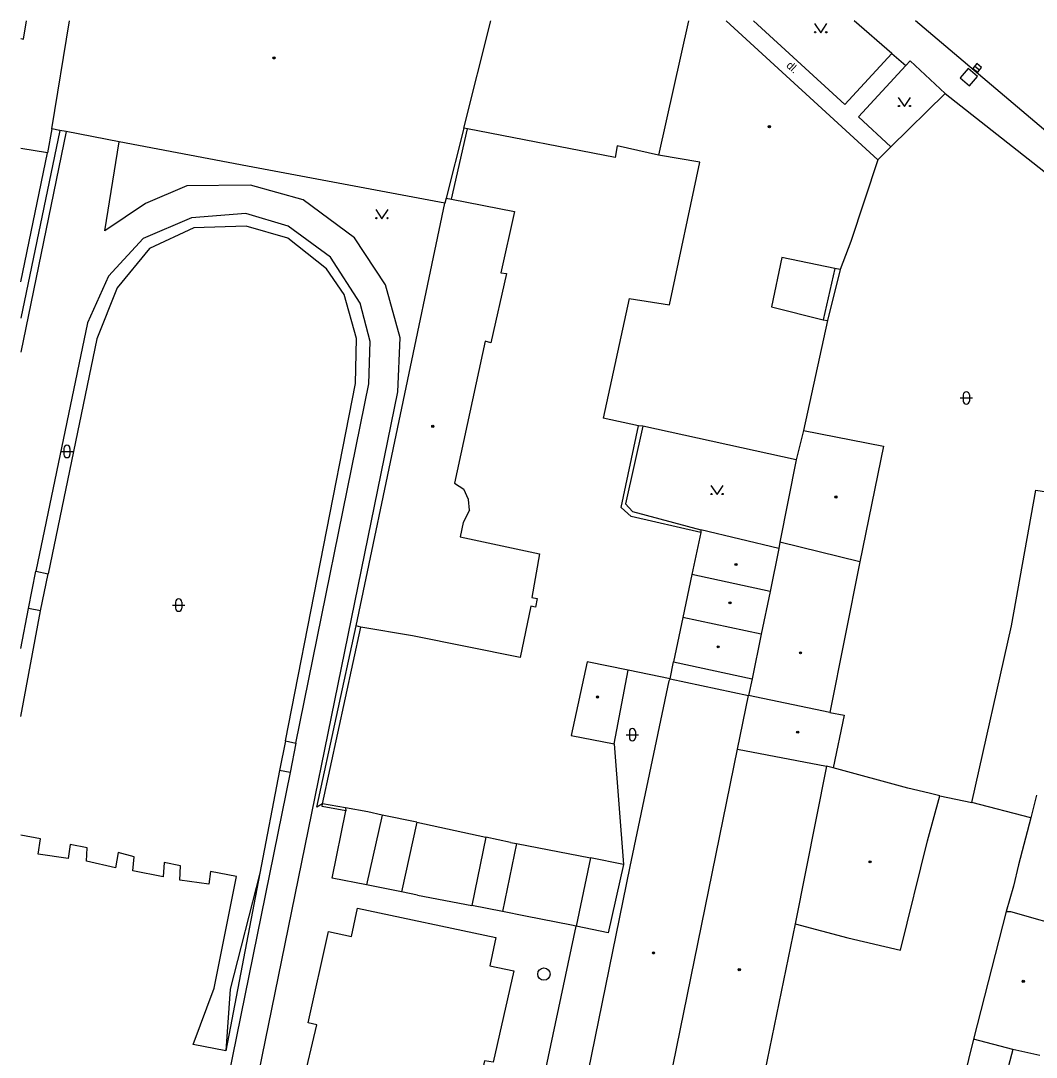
# Model space of a CAD drawing. Extents: x -598932 to -598196, y -1162207 to -1161504.
# Drawn here: x -598932 to -598849.5, y -1161589.4 to -1161505.2 of the extents above; entities that cross this region are included whole.
import ezdxf

# ---------------------------------------------------------------- set-up
doc = ezdxf.new("R2010")
doc.units = 0
for name, color, linetype in [('DOP - budovy nerozlisene - VP', 7, 'Continuous'), ('DOP - kresba z DSPS bez soueadnic', 7, 'Continuous'), ('DOP - rozhrani ploch obecne', 7, 'Continuous'), ('Level 26', 7, 'Continuous'), ('Level 27', 7, 'Continuous'), ('Level 36', 7, 'Continuous'), ('Level 39', 7, 'Continuous'), ('TM - budovy zdene_ betonove - VP', 7, 'Continuous'), ('TM - chodniky - VP', 7, 'Continuous'), ('TM - komunikace - VP', 7, 'Continuous'), ('TM - letecke snimky - pomocna linie', 7, 'Continuous'), ('TM - plot zdeny_ ohradni zed - VP', 7, 'Continuous'), ('TM - popis povrchu', 7, 'Continuous'), ('TM - rozhrani ploch obecne - VP', 7, 'Continuous')]:
    doc.layers.add(name, color=color, linetype=linetype)

msp = doc.modelspace()

# ---------------------------------------------------------------- linework, layer by layer
at = {"layer": 'DOP - budovy nerozlisene - VP'}
for points in [[(-598859.97, -1161567.52), (-598866.02, -1161565.87)], [(-598858.23, -1161567.94), (-598859.97, -1161567.52)], [(-598857.38, -1161568.16), (-598858.23, -1161567.94)], [(-598902.67, -1161569.72), (-598903.92, -1161575.39)], [(-598899.85, -1161570.3), (-598901.1, -1161575.95)], [(-598894.23, -1161571.52), (-598895.38, -1161577.06)], [(-598891.76, -1161572.02), (-598892.9, -1161577.54)], [(-598885.75, -1161573.2), (-598886.91, -1161578.75)], [(-598917.96, -1161612.26), (-598914.54, -1161614.14), (-598913.14, -1161611.53), (-598914.08, -1161611.13), (-598909.68, -1161591.58), (-598909.13, -1161591.69), (-598907.97, -1161586.75), (-598908.67, -1161586.59), (-598907.03, -1161579.17), (-598905.16, -1161579.58), (-598904.66, -1161577.29), (-598893.42, -1161579.66), (-598893.91, -1161581.97), (-598891.98, -1161582.38), (-598893.65, -1161589.78), (-598894.34, -1161589.68), (-598895.47, -1161594.7), (-598894.81, -1161594.85), (-598897.59, -1161607.46)]]:
    msp.add_lwpolyline(points, dxfattribs=at)
at = {"layer": 'DOP - kresba z DSPS bez soueadnic'}
for points in [[(-598928.84, -1161514.09), (-598932.017, -1161529.353)], [(-598928.32, -1161514.19), (-598932.017, -1161532.117)], [(-598897.03, -1161519.69), (-598895.72, -1161513.97)], [(-598925.19, -1161522.26), (-598924.03, -1161515.01)], [(-598918.53, -1161518.6), (-598921.88, -1161520.03)], [(-598913.35, -1161518.55), (-598918.53, -1161518.6)], [(-598909.08, -1161519.72), (-598913.35, -1161518.55)], [(-598921.88, -1161520.03), (-598925.19, -1161522.26)], [(-598904.92, -1161522.82), (-598909.08, -1161519.72)], [(-598913.73, -1161520.84), (-598918.15, -1161521.19)], [(-598910.3, -1161521.87), (-598913.73, -1161520.84)], [(-598918.15, -1161521.19), (-598922.07, -1161522.87)], [(-598917.97, -1161522), (-598921.56, -1161523.69)], [(-598913.71, -1161521.87), (-598917.97, -1161522)], [(-598910.32, -1161522.84), (-598913.71, -1161521.87)], [(-598906.85, -1161524.39), (-598910.3, -1161521.87)], [(-598922.07, -1161522.87), (-598924.88, -1161525.92)], [(-598907.18, -1161525.33), (-598910.32, -1161522.84)], [(-598902.39, -1161526.64), (-598904.92, -1161522.82)], [(-598921.56, -1161523.69), (-598924.18, -1161526.88)], [(-598904.44, -1161528.13), (-598906.85, -1161524.39)], [(-598924.88, -1161525.92), (-598926.59, -1161529.72)], [(-598905.76, -1161527.41), (-598907.18, -1161525.33)], [(-598865.9, -1161525.32), (-598866.84, -1161529.47)], [(-598924.18, -1161526.88), (-598925.84, -1161531.03)], [(-598901.2, -1161530.95), (-598902.39, -1161526.64)], [(-598904.74, -1161531.01), (-598905.76, -1161527.41)], [(-598903.63, -1161531.24), (-598904.44, -1161528.13)], [(-598926.59, -1161529.72), (-598930.78, -1161549.91)], [(-598925.84, -1161531.03), (-598929.8, -1161550.11)], [(-598904.84, -1161534.64), (-598904.74, -1161531.01)], [(-598901.38, -1161535.33), (-598901.2, -1161530.95)], [(-598903.75, -1161534.68), (-598903.63, -1161531.24)], [(-598910.52, -1161563.67), (-598904.84, -1161534.64)], [(-598909.68, -1161563.88), (-598903.75, -1161534.68)], [(-598914.03, -1161597.3), (-598901.38, -1161535.33)], [(-598883.25, -1161544.74), (-598881.85, -1161538.09)], [(-598881.5, -1161538.11), (-598882.91, -1161544.42)], [(-598882.91, -1161544.42), (-598882.33, -1161545.06)], [(-598882.45, -1161545.46), (-598883.25, -1161544.74)], [(-598882.33, -1161545.06), (-598876.77, -1161546.54)], [(-598876.78, -1161546.76), (-598882.45, -1161545.46)], [(-598931.38, -1161552.94), (-598930.78, -1161549.91)], [(-598930.78, -1161549.91), (-598929.8, -1161550.11)], [(-598930.4, -1161553.13), (-598929.8, -1161550.11)], [(-598932.017, -1161556.189), (-598931.38, -1161552.94)], [(-598930.4, -1161553.13), (-598931.38, -1161552.94)], [(-598932.017, -1161561.702), (-598930.4, -1161553.13)], [(-598907.51, -1161568.8), (-598904.39, -1161554.44)], [(-598910.52, -1161563.67), (-598911, -1161566.09)], [(-598910.52, -1161563.67), (-598909.68, -1161563.88)], [(-598909.68, -1161563.88), (-598910.12, -1161566.25)], [(-598910.12, -1161566.25), (-598916.18, -1161595.96)], [(-598911, -1161566.09), (-598912.59, -1161574.44)], [(-598910.12, -1161566.25), (-598911, -1161566.09)], [(-598907.54, -1161569.03), (-598907.51, -1161568.8)], [(-598905.62, -1161569.36), (-598907.54, -1161569.03)], [(-598930.42, -1161571.64), (-598932.017, -1161571.336)], [(-598930.61, -1161572.88), (-598930.42, -1161571.64)], [(-598928, -1161572.11), (-598928.16, -1161573.25)], [(-598926.63, -1161572.37), (-598928, -1161572.11)], [(-598928.16, -1161573.25), (-598930.61, -1161572.88)], [(-598926.68, -1161573.46), (-598926.63, -1161572.37)], [(-598924.1, -1161572.76), (-598924.32, -1161573.99)], [(-598922.81, -1161573.1), (-598924.1, -1161572.76)], [(-598922.9, -1161574.25), (-598922.81, -1161573.1)], [(-598924.32, -1161573.99), (-598926.68, -1161573.46)], [(-598920.37, -1161573.57), (-598920.46, -1161574.72)], [(-598919.04, -1161573.83), (-598920.37, -1161573.57)], [(-598919.09, -1161574.99), (-598919.04, -1161573.83)], [(-598920.46, -1161574.72), (-598922.9, -1161574.25)], [(-598916.6, -1161574.29), (-598916.73, -1161575.34)], [(-598914.48, -1161574.7), (-598916.6, -1161574.29)], [(-598916.3, -1161583.77), (-598914.48, -1161574.7)], [(-598912.59, -1161574.44), (-598915.36, -1161588.86)], [(-598912.59, -1161574.44), (-598915.02, -1161583.85)], [(-598916.73, -1161575.34), (-598919.09, -1161574.99)], [(-598918.02, -1161588.36), (-598916.3, -1161583.77)], [(-598915.02, -1161583.85), (-598915.36, -1161588.86)], [(-598915.36, -1161588.86), (-598918.02, -1161588.36)]]:
    msp.add_lwpolyline(points, dxfattribs=at)
at = {"layer": 'DOP - rozhrani ploch obecne'}
for points in [[(-598932.017, -1161526.398), (-598929.847, -1161515.902)], [(-598865.45, -1161525.39), (-598866.48, -1161529.54)], [(-598907.97, -1161569.08), (-598904.76, -1161554.35)], [(-598879.28, -1161558.65), (-598882.67, -1161557.94)], [(-598879.28, -1161558.65), (-598878.99, -1161557.27)], [(-598883.82, -1161563.92), (-598883.07, -1161573.72)], [(-598907.51, -1161568.8), (-598907.97, -1161569.08)], [(-598905.64, -1161569.12), (-598907.51, -1161568.8)], [(-598891.02, -1161598.13), (-598886.91, -1161578.75)]]:
    msp.add_lwpolyline(points, dxfattribs=at)
at = {"layer": 'Level 26'}
msp.add_lwpolyline([(-598855.725, -1161509.814), (-598854.966, -1161510.465), (-598854.315, -1161509.706), (-598855.074, -1161509.055)], close=True, dxfattribs=at)
at = {"layer": 'Level 27'}
msp.add_line((-598854.526, -1161508.865), (-598854.134, -1161509.175), dxfattribs=at)
msp.add_lwpolyline([(-598854.681, -1161509.062), (-598854.288, -1161509.371), (-598853.979, -1161508.978), (-598854.372, -1161508.669)], close=True, dxfattribs=at)
msp.add_circle((-598889.52, -1161582.63), 0.5, dxfattribs=at)
at = {"layer": 'Level 36'}
for p, q in [((-598855.716, -1161535.826), (-598854.716, -1161535.826)), ((-598855.466, -1161535.576), (-598855.466, -1161536.076)), ((-598854.966, -1161535.576), (-598854.966, -1161536.076)), ((-598928.766, -1161540.176), (-598927.766, -1161540.176)), ((-598928.516, -1161539.926), (-598928.516, -1161540.426)), ((-598928.016, -1161539.926), (-598928.016, -1161540.426)), ((-598919.686, -1161552.656), (-598918.686, -1161552.656)), ((-598919.436, -1161552.406), (-598919.436, -1161552.906)), ((-598918.936, -1161552.406), (-598918.936, -1161552.906)), ((-598882.586, -1161562.936), (-598882.586, -1161563.436)), ((-598882.086, -1161562.936), (-598882.086, -1161563.436)), ((-598882.836, -1161563.186), (-598881.836, -1161563.186))]:
    msp.add_line(p, q, dxfattribs=at)
for points in [[(-598867.54, -1161505.42), (-598867.04, -1161506.17), (-598866.54, -1161505.42)], [(-598860.74, -1161511.41), (-598860.24, -1161512.16), (-598859.74, -1161511.41)], [(-598903.18, -1161520.52), (-598902.68, -1161521.27), (-598902.18, -1161520.52)], [(-598875.96, -1161542.93), (-598875.46, -1161543.68), (-598874.96, -1161542.93)]]:
    msp.add_lwpolyline(points, dxfattribs=at)
for centre in [(-598867.49, -1161506.12), (-598866.591, -1161506.12), (-598860.69, -1161512.11), (-598859.791, -1161512.11), (-598903.13, -1161521.22), (-598902.231, -1161521.22), (-598875.91, -1161543.63), (-598875.011, -1161543.63)]:
    msp.add_circle(centre, 0.05, dxfattribs=at)
for centre, start, end in [((-598855.216, -1161535.576), 0, 180), ((-598855.216, -1161536.076), 180, 0), ((-598928.266, -1161539.926), 0, 180), ((-598928.266, -1161540.426), 180, 0), ((-598919.186, -1161552.406), 0, 180), ((-598919.186, -1161552.906), 180, 0), ((-598882.336, -1161562.936), 0, 180), ((-598882.336, -1161563.436), 180, 0)]:
    msp.add_arc(centre, 0.25, start, end, dxfattribs=at)
at = {"layer": 'Level 39'}
for centre, radius in [((-598911.45, -1161508.2), 0.09), ((-598911.45, -1161508.2), 0.0398), ((-598871.21, -1161513.78), 0.09), ((-598871.21, -1161513.78), 0.0398), ((-598898.55, -1161538.13), 0.09), ((-598898.55, -1161538.13), 0.0398), ((-598865.81, -1161543.87), 0.09), ((-598865.81, -1161543.87), 0.0398), ((-598873.93, -1161549.36), 0.09), ((-598873.93, -1161549.36), 0.0398), ((-598874.41, -1161552.47), 0.09), ((-598874.41, -1161552.47), 0.0398), ((-598875.37, -1161556.05), 0.09), ((-598875.37, -1161556.05), 0.0398), ((-598868.68, -1161556.53), 0.09), ((-598868.68, -1161556.53), 0.0398), ((-598885.17, -1161560.12), 0.09), ((-598885.17, -1161560.12), 0.0398), ((-598868.91, -1161562.98), 0.09), ((-598868.91, -1161562.98), 0.0398), ((-598863.03, -1161573.51), 0.09), ((-598863.03, -1161573.51), 0.0398), ((-598880.62, -1161580.91), 0.09), ((-598880.62, -1161580.91), 0.0398), ((-598873.66, -1161582.27), 0.09), ((-598873.66, -1161582.27), 0.0398), ((-598850.59, -1161583.22), 0.09), ((-598850.59, -1161583.22), 0.0398)]:
    msp.add_circle(centre, radius, dxfattribs=at)
at = {"layer": 'TM - budovy zdene_ betonove - VP'}
for points in [[(-598929.5, -1161513.96), (-598928.053, -1161505.182)], [(-598896.03, -1161513.91), (-598893.826, -1161505.182)], [(-598877.786, -1161505.182), (-598880.21, -1161516.09)], [(-598874.727, -1161505.182), (-598862.41, -1161516.47)], [(-598928.84, -1161514.09), (-598929.5, -1161513.96)], [(-598928.32, -1161514.19), (-598928.84, -1161514.09)], [(-598924.03, -1161515.01), (-598928.32, -1161514.19)], [(-598896.03, -1161513.91), (-598897.46, -1161519.61)], [(-598895.72, -1161513.97), (-598896.03, -1161513.91)], [(-598883.75, -1161516.3), (-598895.72, -1161513.97)], [(-598913.6, -1161516.99), (-598924.03, -1161515.01)], [(-598883.57, -1161515.34), (-598883.75, -1161516.3)], [(-598880.21, -1161516.09), (-598883.57, -1161515.34)], [(-598876.86, -1161516.68), (-598880.21, -1161516.09)], [(-598879.33, -1161528.27), (-598876.86, -1161516.68)], [(-598862.41, -1161516.47), (-598864.6, -1161523.13)], [(-598897.56, -1161520.01), (-598913.6, -1161516.99)], [(-598904.76, -1161554.35), (-598897.56, -1161520.01)], [(-598897.46, -1161519.61), (-598897.56, -1161520.01)], [(-598897.46, -1161519.61), (-598897.03, -1161519.69)], [(-598897.03, -1161519.69), (-598891.9, -1161520.69)], [(-598891.9, -1161520.69), (-598893.01, -1161525.66)], [(-598864.6, -1161523.13), (-598865.45, -1161525.39)], [(-598870.2, -1161524.41), (-598871.04, -1161528.42)], [(-598865.9, -1161525.32), (-598870.2, -1161524.41)], [(-598892.57, -1161525.71), (-598893.84, -1161531.36)], [(-598893.01, -1161525.66), (-598892.57, -1161525.71)], [(-598865.45, -1161525.39), (-598865.9, -1161525.32)], [(-598882.6, -1161527.74), (-598884.7, -1161537.48)], [(-598882.6, -1161527.74), (-598879.33, -1161528.27)], [(-598871.04, -1161528.42), (-598866.84, -1161529.47)], [(-598866.48, -1161529.54), (-598868.44, -1161538.47)], [(-598866.84, -1161529.47), (-598866.48, -1161529.54)], [(-598894.3, -1161531.22), (-598896.78, -1161542.75)], [(-598893.84, -1161531.36), (-598894.3, -1161531.22)], [(-598881.85, -1161538.09), (-598884.7, -1161537.48)], [(-598881.5, -1161538.11), (-598881.85, -1161538.09)], [(-598869.03, -1161540.86), (-598881.5, -1161538.11)], [(-598868.44, -1161538.47), (-598869.03, -1161540.86)], [(-598868.44, -1161538.47), (-598861.94, -1161539.74)], [(-598861.94, -1161539.74), (-598863.86, -1161549.13)], [(-598869.03, -1161540.86), (-598870.35, -1161547.54)], [(-598896.78, -1161542.75), (-598896.04, -1161543.25)], [(-598895.65, -1161544.07), (-598896.04, -1161543.25)], [(-598851.54, -1161554.33), (-598849.56, -1161543.31)], [(-598895.57, -1161544.94), (-598895.65, -1161544.07)], [(-598895.57, -1161544.94), (-598896.09, -1161545.95)], [(-598896.09, -1161545.95), (-598896.33, -1161547.11)], [(-598876.78, -1161546.76), (-598877.5, -1161550.18)], [(-598876.77, -1161546.54), (-598876.78, -1161546.76)], [(-598870.44, -1161548.05), (-598876.77, -1161546.54)], [(-598896.33, -1161547.11), (-598889.88, -1161548.49)], [(-598870.35, -1161547.54), (-598870.44, -1161548.05)], [(-598863.86, -1161549.13), (-598870.35, -1161547.54)], [(-598889.88, -1161548.49), (-598890.5, -1161552.04)], [(-598870.44, -1161548.05), (-598871.16, -1161551.54)], [(-598863.86, -1161549.13), (-598866.29, -1161561.39)], [(-598877.5, -1161550.18), (-598878.23, -1161553.65)], [(-598871.16, -1161551.54), (-598877.5, -1161550.18)], [(-598890.5, -1161552.04), (-598890.06, -1161552.13)], [(-598890.06, -1161552.13), (-598890.2, -1161552.83)], [(-598871.16, -1161551.54), (-598871.88, -1161555.02)], [(-598890.59, -1161552.73), (-598891.46, -1161556.91)], [(-598890.2, -1161552.83), (-598890.59, -1161552.73)], [(-598878.23, -1161553.65), (-598878.99, -1161557.27)], [(-598871.88, -1161555.02), (-598878.23, -1161553.65)], [(-598904.39, -1161554.44), (-598904.76, -1161554.35)], [(-598900.2, -1161555.16), (-598904.39, -1161554.44)], [(-598854.78, -1161568.68), (-598851.54, -1161554.33)], [(-598891.46, -1161556.91), (-598900.2, -1161555.16)], [(-598871.88, -1161555.02), (-598872.62, -1161558.64)], [(-598886.01, -1161557.26), (-598887.32, -1161563.24)], [(-598882.67, -1161557.94), (-598886.01, -1161557.26)], [(-598883.82, -1161563.92), (-598882.67, -1161557.94)], [(-598878.99, -1161557.27), (-598872.62, -1161558.64)], [(-598882.51, -1161573.88), (-598879.34, -1161558.81)], [(-598879.34, -1161558.81), (-598879.28, -1161558.65)], [(-598879.28, -1161558.65), (-598872.91, -1161560.01)], [(-598872.62, -1161558.64), (-598872.91, -1161560.01)], [(-598873.81, -1161564.36), (-598872.91, -1161560.01)], [(-598866.29, -1161561.39), (-598872.91, -1161560.01)], [(-598866.29, -1161561.39), (-598865.15, -1161561.59)], [(-598865.15, -1161561.59), (-598866.02, -1161565.87)], [(-598887.32, -1161563.24), (-598883.82, -1161563.92)], [(-598881.66, -1161602.9), (-598873.81, -1161564.36)], [(-598873.81, -1161564.36), (-598866.56, -1161565.74)], [(-598866.56, -1161565.74), (-598869.12, -1161578.54)], [(-598866.02, -1161565.87), (-598866.56, -1161565.74)], [(-598849.51, -1161568.11), (-598849.98, -1161569.95)], [(-598858.38, -1161571.81), (-598857.38, -1161568.16)], [(-598857.38, -1161568.16), (-598854.78, -1161568.68)], [(-598849.98, -1161569.95), (-598854.78, -1161568.68)], [(-598906.73, -1161574.83), (-598905.62, -1161569.36)], [(-598905.64, -1161569.12), (-598905.62, -1161569.36)], [(-598903.82, -1161569.46), (-598905.64, -1161569.12)], [(-598902.67, -1161569.72), (-598903.82, -1161569.46)], [(-598899.85, -1161570.3), (-598902.67, -1161569.72)], [(-598899.85, -1161570.3), (-598894.23, -1161571.52)], [(-598849.98, -1161569.95), (-598850.97, -1161573.77)], [(-598892.23, -1161571.95), (-598894.23, -1161571.52)], [(-598892.23, -1161571.95), (-598891.76, -1161572.02)], [(-598891.76, -1161572.02), (-598885.75, -1161573.2)], [(-598860.56, -1161580.69), (-598858.38, -1161571.81)], [(-598887.6, -1161598.85), (-598882.51, -1161573.88)], [(-598883.07, -1161573.72), (-598885.75, -1161573.2)], [(-598883.07, -1161573.72), (-598884.31, -1161579.29)], [(-598850.97, -1161573.77), (-598851.39, -1161575.5)], [(-598903.92, -1161575.39), (-598906.73, -1161574.83)], [(-598901.1, -1161575.95), (-598903.92, -1161575.39)], [(-598851.39, -1161575.5), (-598851.99, -1161577.55)], [(-598899.78, -1161576.21), (-598901.1, -1161575.95)], [(-598899.78, -1161576.21), (-598895.38, -1161577.06)], [(-598892.9, -1161577.54), (-598895.38, -1161577.06)], [(-598891.01, -1161577.92), (-598892.9, -1161577.54)], [(-598887.29, -1161578.67), (-598891.01, -1161577.92)], [(-598851.99, -1161577.55), (-598854.63, -1161587.92)], [(-598851.99, -1161577.55), (-598851.63, -1161577.55)], [(-598851.63, -1161577.55), (-598846.68, -1161578.95)], [(-598886.91, -1161578.75), (-598887.29, -1161578.67)], [(-598884.31, -1161579.29), (-598886.91, -1161578.75)], [(-598869.12, -1161578.54), (-598871.58, -1161590.53)], [(-598869.12, -1161578.54), (-598864.83, -1161579.7)], [(-598864.83, -1161579.7), (-598860.56, -1161580.69)], [(-598854.63, -1161587.92), (-598857.08, -1161597.83)], [(-598851.44, -1161588.77), (-598854.63, -1161587.92)], [(-598851.44, -1161588.77), (-598852.27, -1161591.92)], [(-598849.25, -1161589.24), (-598851.44, -1161588.77)]]:
    msp.add_lwpolyline(points, dxfattribs=at)
at = {"layer": 'TM - chodniky - VP'}
for points in [[(-598872.504, -1161505.182), (-598865.08, -1161511.99)], [(-598861.27, -1161507.84), (-598864.335, -1161505.182)], [(-598865.08, -1161511.99), (-598861.27, -1161507.84)], [(-598860.14, -1161508.82), (-598863.97, -1161513), (-598861.34, -1161515.42)], [(-598856.93, -1161511.1), (-598859.78, -1161508.43), (-598860.14, -1161508.82)]]:
    msp.add_lwpolyline(points, dxfattribs=at)
at = {"layer": 'TM - komunikace - VP'}
msp.add_lwpolyline([(-598843.13, -1161518.91), (-598859.353, -1161505.182)], dxfattribs=at)
at = {"layer": 'TM - letecke snimky - pomocna linie'}
for points in [[(-598932.017, -1161506.638), (-598931.79, -1161506.68), (-598931.536, -1161505.182)], [(-598929.5, -1161513.96), (-598929.847, -1161515.902)], [(-598929.847, -1161515.902), (-598932.017, -1161515.555)], [(-598849.56, -1161543.31), (-598843.97, -1161544.21)]]:
    msp.add_lwpolyline(points, dxfattribs=at)
at = {"layer": 'TM - plot zdeny_ ohradni zed - VP'}
for points in [[(-598861.34, -1161515.42), (-598856.93, -1161511.1)], [(-598856.93, -1161511.1), (-598844.73, -1161520.71)], [(-598862.41, -1161516.47), (-598861.34, -1161515.42)]]:
    msp.add_lwpolyline(points, dxfattribs=at)
at = {"layer": 'TM - rozhrani ploch obecne - VP'}
msp.add_lwpolyline([(-598861.27, -1161507.84), (-598860.14, -1161508.82)], dxfattribs=at)

# ---------------------------------------------------------------- texts
at = {"layer": 'TM - popis povrchu'}
msp.add_text('dl.', height=0.65, rotation=317.65, dxfattribs=at).set_placement((-598869.89, -1161508.89))

doc.saveas('drawing.dxf')
